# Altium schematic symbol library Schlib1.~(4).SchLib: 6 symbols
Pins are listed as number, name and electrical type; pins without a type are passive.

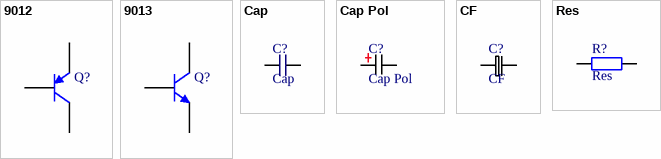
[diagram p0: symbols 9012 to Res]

## 9012
designator Q?  (value not drawn)
PNP General Purpose Amplifier
pins: 1 E, 2 B, 3 C

## 9013
designator Q?  (value not drawn)
NPN General Purpose Amplifier
pins: 1 E, 2 B, 3 C

## Cap
designator C?
pins: 1, 2

## Cap Pol
designator C?
pins: 1, 2

## CF
designator C?
pins: 1, 2

## Res
designator R?
Resistor; Value: 1K
pins: 1, 2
